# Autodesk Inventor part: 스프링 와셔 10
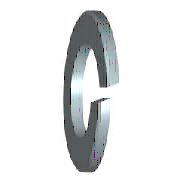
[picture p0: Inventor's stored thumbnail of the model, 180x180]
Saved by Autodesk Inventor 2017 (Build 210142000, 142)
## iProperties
Created: 2012-02
Part Number: 스프링 와셔 10
Material: 강철, 연강
Description: 스프링 잠금 와셔
Document SubType Name: Modeling
Standard: KS B 1324
Designer: mduedu
Standards Organization: KS
Language: ko-KR
Size Designation: 번호 2 - 10
Categories: <MemberInstance><Categories><Category DisplayName="조임쇠" InternalName="e4da775c-781d-43d5-af7c-5136215cf5a6" Mnemonic="FSTN"><Category DisplayName="와셔" InternalN
Density: 1 g/cm^3
Appearance: 강철
IsCustomPart: 1
Author: mduedu
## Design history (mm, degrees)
sketch "스케치1"
  geometry: C1 r 8.8 at (0, 0); C2 r 5.1 at (0, 0); 1 further point
  constraints: 2 centre point, 2 coincident
  dimensions: "d0" = 10.2 diameter of C2 (= SD1); "d1" = 17.6 diameter of C1 (= SD2)
extrude "본체" new body sketch "스케치1" distance "d2" = 2.5 (= SD); taper "d3" = 0 deg
sketch "스케치2"
  geometry: L1 (0, -5.1)-(0, 5.1) reference; L2 (2.5, 8.8)-(2.5, -8.8) reference; L3 (-1.2, 0)-(7.2, 0) reference; L4 (0, -0.5)-(2.5, 0.41); L5 (0, 0.5)-(2.5, 1.41)
  constraints: 4 end point, 4 point on line, 1 parallel
  dimensions: "d4" = 0.5 distance from line of L3 L4.start (= 0.2 x SD); "d5" = 0.5 distance from line of L3 L5.start (= 0.2 x SD); "d6" = 70 deg angle of L2 L4 (= FAWI)
extrude "절단부" cut sketch "스케치2" stored distance "d7" = 2.5 (= SD); taper "d8" = 0 deg
workaxis "Work Axis1"
workplane "Work Plane1"
body "Solid1"
other parameters: "SD1" = 10.2 [user parameter; used in 1 equation term], "SD2" = 17.6 [user parameter; used in 1 equation term], "SD" = 2.5 [user parameter; used in 4 equation terms], "FAWI" = 70 deg [user parameter; used in 1 equation term], "d9" = 0, "d10" = 0, "d11" = 0, "d12" = 0, "SDI" = 3.7 [user parameter]
